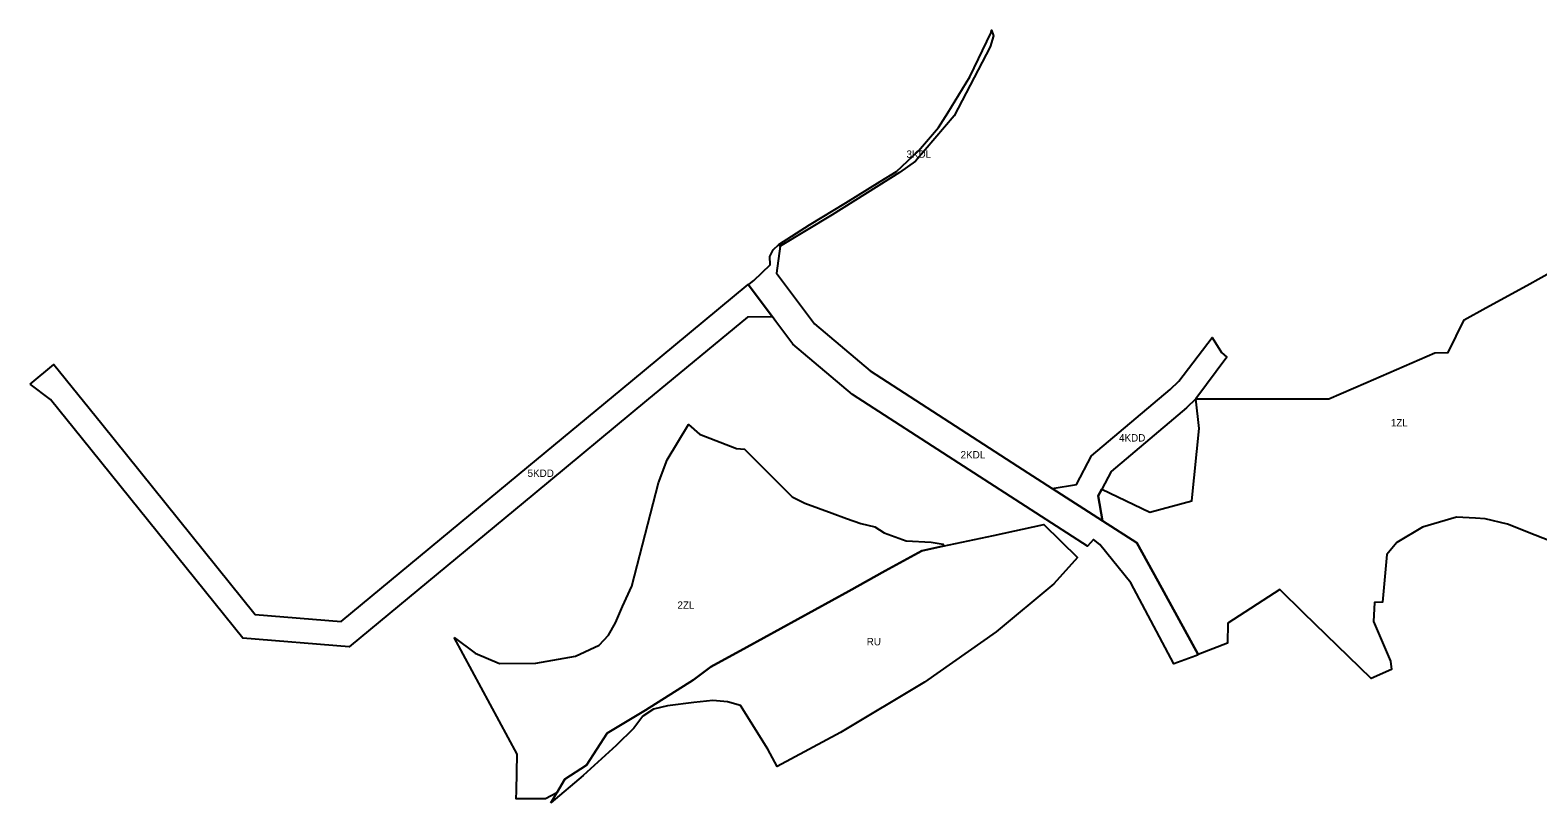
# Model space of a CAD drawing. Extents: x 7426456 to 7427896, y 5541728 to 5542811.
# Drawn here: x 7426458 to 7427071, y 5541931 to 5542245 of the extents above; entities that cross this region are included whole.
import ezdxf

# ---------------------------------------------------------------- set-up
doc = ezdxf.new("R2010")
doc.units = 0
doc.layers.add('ramka', color=7, linetype='Continuous')
doc.layers.add('sekcje2000', color=7, linetype='Continuous')

msp = doc.modelspace()

# ---------------------------------------------------------------- linework, layer by layer
at = {"layer": 'ramka'}
for points in [[(7426762.56, 5542157.82), (7426775.02, 5542165.75), (7426789.74, 5542174.81), (7426803.75, 5542183.42), (7426810.37, 5542187.5), (7426819.34, 5542195.84), (7426827.56, 5542205.39), (7426831.33, 5542211.32), (7426840.23, 5542225.92), (7426848.9, 5542244.01), (7426849.06, 5542244.94), (7426849.94, 5542242.63), (7426848.58, 5542238.17), (7426833.91, 5542210.1), (7426818.12, 5542191.71), (7426811.69, 5542187.13), (7426784.17, 5542169.84), (7426763.08, 5542157.12)], [(7426750.09, 5542141.49), (7426750.4, 5542141.74), (7426752.36, 5542143.14), (7426759.03, 5542149.52), (7426758.81, 5542152.88), (7426760.2, 5542155.67), (7426762.56, 5542157.82), (7426763.08, 5542157.12), (7426761.58, 5542146.18), (7426777.07, 5542125.62), (7426799.64, 5542106.45), (7426859.68, 5542067.76), (7426873.81, 5542058.65), (7426894.27, 5542045.47), (7426908.21, 5542036.48), (7426916.87, 5542020.75), (7426933.21, 5541991.07), (7426932.77, 5541990.9), (7426932.14, 5541990.65), (7426923.28, 5541987.33), (7426905.8, 5542020.3), (7426893.13, 5542035.85), (7426890.55, 5542037.92), (7426888.1, 5542035.16), (7426835.8, 5542068.88), (7426792.48, 5542096.79), (7426768.29, 5542117.33), (7426761.37, 5542126.51), (7426759.97, 5542128.38)], [(7426457.89, 5542101.04), (7426467.55, 5542109), (7426486.99, 5542084.9), (7426549.51, 5542007.42), (7426584.4, 5542004.6), (7426656.91, 5542064.5), (7426702.36, 5542102.05), (7426750.09, 5542141.49), (7426759.97, 5542128.38), (7426749.81, 5542128.28), (7426708.73, 5542094.34), (7426663.27, 5542056.79), (7426587.64, 5541994.31), (7426544.42, 5541997.8), (7426479.21, 5542078.62), (7426466.11, 5542094.86)], [(7426873.81, 5542058.65), (7426883.67, 5542060.29), (7426889.78, 5542071.9), (7426907.97, 5542087.24), (7426921.72, 5542098.83), (7426925.26, 5542102.23), (7426938.8, 5542120.02), (7426942.64, 5542113.9), (7426944.79, 5542112.04), (7426932.18, 5542095.01), (7426928.41, 5542091.39), (7426923.11, 5542086.92), (7426897.72, 5542065.52), (7426893.97, 5542058.38), (7426892.52, 5542055.63), (7426894.27, 5542045.47)], [(7426630.42, 5541998.09), (7426638.99, 5541991.71), (7426648.9, 5541987.41), (7426663.61, 5541987.56), (7426679.77, 5541990.51), (7426689.42, 5541994.88), (7426693.23, 5541999), (7426696.02, 5542003.97), (7426698.98, 5542010.68), (7426702.65, 5542018.98), (7426713.5, 5542060.96), (7426717.08, 5542070.32), (7426725.83, 5542084.61), (7426730.28, 5542080.7), (7426745.35, 5542074.9), (7426748.54, 5542074.61), (7426753.44, 5542069.71), (7426758.22, 5542064.93), (7426763.07, 5542060.1), (7426767.91, 5542055.26), (7426773.1, 5542052.61), (7426778.66, 5542050.61), (7426784.22, 5542048.6), (7426790.08, 5542046.49), (7426795.94, 5542044.38), (7426801.62, 5542043.09), (7426805.41, 5542040.66), (7426814.32, 5542037.32), (7426824.55, 5542036.84), (7426829.4, 5542035.97), (7426829.3, 5542035.14), (7426820.74, 5542033.28), (7426805.86, 5542025.1), (7426790.98, 5542016.92), (7426770.22, 5542005.5), (7426749.47, 5541994.08), (7426734.91, 5541986.07), (7426727.75, 5541980.88), (7426708.34, 5541968.53), (7426692.64, 5541959.16), (7426684.3, 5541946.13), (7426675.48, 5541940.47), (7426672.19, 5541934.96), (7426667.6, 5541932.47), (7426655.59, 5541932.51), (7426655.73, 5541935.72), (7426656.11, 5541950.58)], [(7426669.72, 5541930.84), (7426672.19, 5541934.96), (7426675.48, 5541940.47), (7426684.3, 5541946.13), (7426692.64, 5541959.16), (7426708.34, 5541968.53), (7426727.75, 5541980.88), (7426734.91, 5541986.07), (7426749.47, 5541994.08), (7426770.22, 5542005.5), (7426790.98, 5542016.92), (7426805.86, 5542025.1), (7426820.74, 5542033.28), (7426829.3, 5542035.14), (7426849.82, 5542039.58), (7426870.34, 5542044.03), (7426884.04, 5542030.6), (7426874.47, 5542019.85), (7426850.95, 5542000.31), (7426821.75, 5541979.88), (7426787.63, 5541959.48), (7426761.89, 5541945.61), (7426758.04, 5541952.6), (7426746.87, 5541970.41), (7426741.69, 5541971.87), (7426735.69, 5541972.47), (7426727.96, 5541971.6), (7426717.17, 5541970.27), (7426711.57, 5541968.92), (7426707.15, 5541966.05), (7426703.51, 5541961.25), (7426696.32, 5541954.15), (7426682.88, 5541941.91)]]:
    msp.add_lwpolyline(points, close=True, dxfattribs=at)
msp.add_lwpolyline([(7427076.46, 5542037.26), (7427070.23, 5542039.71), (7427058.98, 5542044.16), (7427049.9, 5542046.3), (7427045.97, 5542046.5), (7427038.28, 5542046.91), (7427024.5, 5542042.95), (7427014.03, 5542036.72), (7427009.96, 5542031.8), (7427008.22, 5542012.36), (7427004.94, 5542012.24), (7427004.55, 5542004.5), (7427011.48, 5541988.42), (7427011.87, 5541985.08), (7427003.52, 5541981.41), (7426976.04, 5542008.13), (7426966.38, 5542017.53), (7426945.26, 5542003.94), (7426945.08, 5541995.8), (7426933.21, 5541991.07), (7426916.87, 5542020.75), (7426908.21, 5542036.48), (7426894.27, 5542045.47), (7426892.52, 5542055.63), (7426893.97, 5542058.38), (7426913.53, 5542049.03), (7426930.59, 5542053.6), (7426933.56, 5542083.07), (7426932.18, 5542095.01), (7426986.34, 5542095.03), (7427001.36, 5542101.56), (7427029.51, 5542113.79), (7427034.83, 5542113.88), (7427041.4, 5542127.2), (7427050.16, 5542132.02), (7427066.85, 5542141.19), (7427078.62, 5542147.67)], dxfattribs=at)

# ---------------------------------------------------------------- texts
at = {"layer": 'sekcje2000'}
for s, p in [('3KDL', (7426814.47, 5542193.06)), ('1ZL', (7427011.55, 5542083.86)), ('4KDD', (7426900.96, 5542077.72)), ('2KDL', (7426836.49, 5542070.83)), ('5KDD', (7426660.29, 5542063.33)), ('2ZL', (7426721.27, 5542009.71)), ('RU', (7426798.28, 5541994.86))]:
    msp.add_text(s, height=3, dxfattribs=at).set_placement(p)

doc.saveas('drawing.dxf')
